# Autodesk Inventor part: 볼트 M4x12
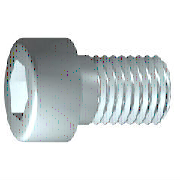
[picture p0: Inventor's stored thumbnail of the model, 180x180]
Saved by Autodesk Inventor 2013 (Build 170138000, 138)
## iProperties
IsCustomPart: 0
Created: 2012-02
Part Number: 볼트 M4x12
Material: 강철, 연강
Description: 6각 소켓 머리 캡 나사
Document SubType Name: Modeling
Standard: ISO 4762
Designer: mduedu
Standard Revision: Fourth edition 2004-03-01
Standards Organization: ISO
Language: ko-KR
Size Designation: M4 x 12
Categories: <MemberInstance><Categories><Category DisplayName="조임쇠" InternalName="e4da775c-781d-43d5-af7c-5136215cf5a6" Mnemonic="FSTN"><Category DisplayName="볼트" InternalN
Density: 7.75 g/cm^3
Author: mduedu
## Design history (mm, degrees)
sketch "스케치1"
  geometry: L1 (-1, 0)-(12, 0); L2 (12, 0)-(12, 2); L3 (12, 2)-(1.75, 2); L4 (1.75, 2)-(1.32, 2); L5 (1.32, 2)-(0, 2); L6 (0, 2)-(0, 3.5); L7 (0, 3.5)-(-4, 3.5); L8 (-4, 3.5)-(-4, 1.732); L9 (-4, 1.732)-(-2, 1.732); L10 (-2, 1.732)-(-1, 0); L11 (-7.2, 0)-(15.2, 0) reference; L12 (0, -0.7)-(0, 4.2) reference; L13 (1.75, 2)-(0, 2)
  constraints: 22 end point, 6 parallel, 2 collinear, 2 perpendicular, 1 horizontal, 1 point on line
  dimensions: "d1" = 10.25 distance from line of L3.end L2 (= GEL); "d2" = 0.42952 distance of L4.end L3.end (computed from GAL); "d3" = 4 distance between parallel lines of L8 L6 (= KOH); "d4" = 2 distance of L8.end L9.end (= INTI); "d5" = 60 deg angle of L10 L1; "d6" = 4 diameter of L3 L1 (= GD); "d7" = 4 diameter of L5 L1 (= BDM); "d8" = 3.4641 diameter of L9 L1 (= 1.1547 x SW); "d9" = 7 diameter of L7 L1 (= KOD); "d26" = 12 distance between parallel lines of L12 L2 (= NLG)
revolve "본체" sketch "스케치1" stored, may be unused: angle "d10" = 90 deg
sketch "스케치2"
  geometry: L1 (0, -4.9)-(0, 4.9) reference; L2 (-4.9, 0)-(4.9, 0) reference; L3 (1.732, 0)-(0.866, -1.5); L4 (0.866, -1.5)-(-0.866, -1.5); L5 (-0.866, -1.5)-(-1.732, 0); L6 (-1.732, 0)-(-0.866, 1.5); L7 (-0.866, 1.5)-(0.866, 1.5); L8 (0.866, 1.5)-(1.732, 0); 2 further points
  constraints: 12 end point, 1 coincident, 1 horizontal alignment, 1 point on line, 12 other
extrude "슬롯" join sketch "스케치2" stored distance "d11" = 10; taper "d12" = 0 deg
workplane "Work Plane1"
fillet "Fillet2" dims "d30" = 0.1 (= R)
body "Solid1"
fillet "모깎기1" dims "d17" = 0.4 (= RR)
feature "스레드" dims "d13" = 10.25 (= GEL), "d14" = 0
chamfer "모따기1" distance "d15" = 0.42941 (= -0.5 x SPD + 0.5 x GD); stored, may be unused: second distance "d16" = 0.42941 (= GUL), angle "d27" = 45 deg
other parameters: "GD" = 4 [user parameter; used in 2 equation terms], "NLG" = 12 [user parameter; used in 1 equation term], "GEL" = 10.25 [user parameter; used in 2 equation terms], "KOD" = 7 [user parameter; used in 1 equation term], "KOH" = 4 [user parameter; used in 1 equation term], "INTI" = 2 [user parameter; used in 1 equation term], "GAL" = 0.42941 (= 0.61345 x PTC) [user parameter; used in 1 equation term], "GUL" = 0.42941 (= 0.61345 x PTC) [user parameter; used in 1 equation term], "BDM" = 4 (= NND) [user parameter; used in 1 equation term], "SW" = 3 [user parameter; used in 2 equation terms], "RR" = 0.4 [user parameter; used in 1 equation term], "SPD" = 3.14117 (= NND - 1.2269 x PTC) [user parameter; used in 1 equation term], "d19" = 0, "d28" = 0, "d29" = 0, "R" = 0.1 [user parameter; used in 1 equation term], "TOA" = 30 deg [user parameter], "GD1" = 3.14117 (= THREADDIA - 1.2269 x PTC) [user parameter], "THREADDIA" = 4 [user parameter; used in 1 equation term], "FAWI" = 45 deg [user parameter], "TPU" = 14.28571 (computed from PTC) [user parameter], "PTC" = 0.7 [user parameter; used in 5 equation terms], "NND" = 4 [user parameter; used in 2 equation terms], "E0" = 3.465 (= 1.155 x SW) [user parameter]
